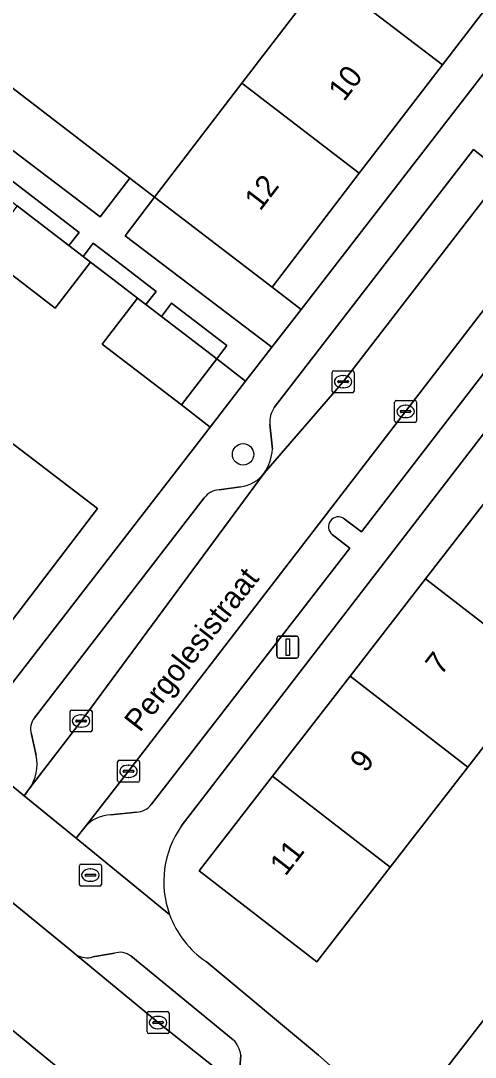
# Model space of a CAD drawing. Extents: x 159039 to 160102, y 381214 to 382524.
# Drawn here: x 159263.73 to 159284.46, y 381529.08 to 381576.34 of the extents above; entities that cross this region are included whole.
import ezdxf

# ---------------------------------------------------------------- set-up
doc = ezdxf.new("R2010")
doc.units = 0
for name, color, linetype in [('IMGEO_Boom', 7, 'Continuous'), ('IMGEO_Brandkraan', 7, 'Continuous'), ('IMGEO_Erf', 7, 'Continuous'), ('IMGEO_Groenvoorziening', 7, 'Continuous'), ('IMGEO_Kolk', 7, 'Continuous'), ('IMGEO_Lichtmast', 7, 'Continuous'), ('IMGEO_Openbare_ruimte_label', 7, 'Continuous'), ('IMGEO_Pand', 7, 'Continuous'), ('IMGEO_Pand_nummerreeks', 7, 'Continuous'), ('IMGEO_Parkeervlak_open', 7, 'Continuous'), ('IMGEO_Rijbaan_lokaal_open', 7, 'Continuous'), ('IMGEO_Voetpad_open', 7, 'Continuous')]:
    doc.layers.add(name, color=color, linetype=linetype)

msp = doc.modelspace()

# ---------------------------------------------------------------- linework, layer by layer
at = {"layer": 'IMGEO_Boom'}
msp.add_circle((159273.87, 381556.568), 0.489, dxfattribs=at)
at = {"layer": 'IMGEO_Brandkraan'}
for p, q in [((159266.408, 381536.956), (159266.408, 381537.808)), ((159266.483, 381537.882), (159267.335, 381537.882)), ((159266.896, 381537.662), (159266.921, 381537.662)), ((159267.409, 381537.808), (159267.409, 381536.956)), ((159266.667, 381537.376), (159266.667, 381537.388)), ((159267.105, 381537.339), (159266.707, 381537.339)), ((159266.71, 381537.425), (159267.108, 381537.425)), ((159266.919, 381537.102), (159266.894, 381537.102)), ((159267.151, 381537.388), (159267.151, 381537.376)), ((159267.335, 381536.882), (159266.483, 381536.882))]:
    msp.add_line(p, q, dxfattribs=at)
for points in [[(159266.408, 381536.956), (159266.408, 381537.808)], [(159266.483, 381537.882), (159267.335, 381537.882)], [(159267.409, 381537.808), (159267.409, 381536.956)], [(159267.335, 381536.882), (159266.483, 381536.882)]]:
    msp.add_lwpolyline(points, dxfattribs=at)
for centre, radius, start, end in [((159266.485, 381537.806), 0.0765, 91.552, 178.448), ((159266.485, 381537.806), 0.0765, 91.552, 178.448), ((159267.333, 381537.806), 0.0765, 1.552, 88.448), ((159267.333, 381537.806), 0.0765, 1.552, 88.448), ((159266.707, 381537.385), 0.0403, 85.8775, 175.7526), ((159266.704, 381537.375), 0.0366, 178.938, 274.7102), ((159267.108, 381537.382), 0.043, 264.8664, 352.4533), ((159267.112, 381537.387), 0.0386, 1.7309, 96.639), ((159266.485, 381536.958), 0.0765, 181.552, 268.448), ((159266.485, 381536.958), 0.0765, 181.552, 268.448), ((159267.333, 381536.958), 0.0765, 271.552, 358.448), ((159267.333, 381536.958), 0.0765, 271.552, 358.448)]:
    msp.add_arc(centre, radius, start, end, dxfattribs=at)
for centre, major_axis, ratio, start_param, end_param in [((159266.895, 381537.382), (-0.387, 0.002), 0.722429, 4.712389, 7.853982), ((159266.92, 381537.382), (-0.39, 0.002), 0.717154, 1.570796, 4.712389)]:
    msp.add_ellipse(centre, major_axis=major_axis, ratio=ratio, start_param=start_param, end_param=end_param, dxfattribs=at)
at = {"layer": 'IMGEO_Erf'}
for points in [[(159299.551, 381592.96), (159298.091, 381594.079), (159294.348, 381589.194), (159290.532, 381584.215), (159286.641, 381579.137), (159282.958, 381574.331), (159279.168, 381569.384), (159275.191, 381564.195), (159276.512, 381563.173)], [(159284.112, 381542.306), (159280.576, 381537.741), (159277.232, 381533.425), (159271.871, 381537.579), (159275.215, 381541.895), (159278.751, 381546.459), (159282.191, 381550.899), (159285.558, 381555.245), (159289.08, 381559.791), (159292.511, 381564.22), (159297.872, 381560.066), (159294.441, 381555.638), (159290.919, 381551.092), (159287.552, 381546.746)]]:
    msp.add_lwpolyline(points, close=True, dxfattribs=at)
for points in [[(159259.234, 381576.433), (159268.71, 381569.162), (159269.835, 381568.299), (159273.812, 381573.488), (159277.602, 381578.435)], [(159261.962, 381565.796), (159257.471, 381569.237), (159254.749, 381571.323), (159254.989, 381569.613), (159254.037, 381568.427), (159252.746, 381568.172), (159251.602, 381568.976), (159251.387, 381570.516), (159248.601, 381566.929), (159247.971, 381566.118), (159252.45, 381562.686), (159256.94, 381559.245), (159261.298, 381555.906), (159261.655, 381555.632), (159262.975, 381557.354), (159267.229, 381554.093), (159265.91, 381552.372), (159261.821, 381547.037), (159257.209, 381550.571), (159252.851, 381553.911), (159248.361, 381557.351), (159243.882, 381560.783), (159241.386, 381557.502), (159258.08, 381544.802)], [(159296.955, 381546.416), (159299.454, 381549.642), (159301.579, 381547.996), (159302.602, 381549.316), (159300.477, 381550.962), (159303.956, 381555.453), (159306.081, 381553.807), (159307.411, 381555.524), (159307.658, 381555.842), (159293.244, 381568.431), (159292.895, 381567.979), (159271.052, 381539.613)], [(159262.507, 381545.066), (159272.367, 381557.814), (159271.062, 381558.823), (159267.444, 381561.595), (159269.054, 381563.696), (159267.929, 381564.558), (159266.916, 381565.334), (159265.306, 381563.234), (159261.962, 381565.796)], [(159272.188, 381533.437), (159277.302, 381529.172), (159283.05, 381524.08), (159285.339, 381527.035), (159283.214, 381528.681), (159286.611, 381533.065), (159290.148, 381537.63), (159292.453, 381540.606), (159294.578, 381538.96), (159295.713, 381540.424), (159297.219, 381542.368), (159295.094, 381544.014), (159296.955, 381546.416)]]:
    msp.add_lwpolyline(points, dxfattribs=at)
for centre, radius, start, end in [((159274.663, 381537.084), 4.409, 144.9927, 199.8758), ((159274.669, 381537.091), 4.417, 199.9364, 235.8246)]:
    msp.add_arc(centre, radius, start, end, dxfattribs=at)
at = {"layer": 'IMGEO_Groenvoorziening'}
for points in [[(159259.234, 381576.433), (159257.173, 381578.013), (159256.868, 381577.615), (159255.768, 381576.179), (159267.355, 381567.397), (159268.71, 381569.162)], [(159261.697, 381570.29), (159261.236, 381569.688), (159263.573, 381567.897), (159265.93, 381566.09), (159266.392, 381566.692)], [(159269.835, 381568.299), (159268.496, 381566.532), (159275.188, 381561.461), (159276.512, 381563.173), (159275.191, 381564.195)], [(159268.31, 381565.221), (159267.034, 381566.199), (159266.573, 381565.597), (159266.916, 381565.334), (159267.929, 381564.558), (159269.054, 381563.696), (159269.443, 381563.398), (159269.904, 381564)], [(159270.611, 381563.458), (159270.15, 381562.856), (159272.672, 381560.924), (159273.133, 381561.526)], [(159273.986, 381559.907), (159272.672, 381560.924), (159271.062, 381558.823), (159272.367, 381557.814)]]:
    msp.add_lwpolyline(points, close=True, dxfattribs=at)
at = {"layer": 'IMGEO_Kolk'}
for p, q in [((159277.931, 381559.455), (159277.931, 381560.307)), ((159278.006, 381560.381), (159278.858, 381560.381)), ((159278.932, 381560.307), (159278.932, 381559.455)), ((159278.19, 381559.875), (159278.19, 381559.887)), ((159278.628, 381559.838), (159278.23, 381559.838)), ((159278.233, 381559.924), (159278.631, 381559.924)), ((159278.419, 381560.161), (159278.444, 381560.161)), ((159278.674, 381559.887), (159278.674, 381559.875)), ((159278.858, 381559.381), (159278.006, 381559.381)), ((159278.442, 381559.601), (159278.417, 381559.601)), ((159280.781, 381558.098), (159280.781, 381558.95)), ((159280.856, 381559.024), (159281.708, 381559.024)), ((159281.269, 381558.804), (159281.294, 381558.804)), ((159281.782, 381558.95), (159281.782, 381558.098)), ((159281.04, 381558.518), (159281.04, 381558.53)), ((159281.478, 381558.481), (159281.08, 381558.481)), ((159281.083, 381558.567), (159281.481, 381558.567)), ((159281.524, 381558.53), (159281.524, 381558.518)), ((159281.708, 381558.024), (159280.856, 381558.024)), ((159281.292, 381558.244), (159281.267, 381558.244)), ((159265.983, 381543.983), (159265.983, 381544.835)), ((159266.058, 381544.909), (159266.91, 381544.909)), ((159266.471, 381544.689), (159266.496, 381544.689)), ((159266.984, 381544.835), (159266.984, 381543.983)), ((159266.242, 381544.403), (159266.242, 381544.415)), ((159266.68, 381544.366), (159266.282, 381544.366)), ((159266.285, 381544.452), (159266.683, 381544.452)), ((159266.494, 381544.129), (159266.469, 381544.129)), ((159266.726, 381544.415), (159266.726, 381544.403)), ((159266.91, 381543.909), (159266.058, 381543.909)), ((159268.145, 381541.691), (159268.145, 381542.543)), ((159268.22, 381542.617), (159269.072, 381542.617)), ((159268.633, 381542.397), (159268.658, 381542.397)), ((159269.146, 381542.543), (159269.146, 381541.691)), ((159268.404, 381542.111), (159268.404, 381542.123)), ((159268.842, 381542.074), (159268.444, 381542.074)), ((159268.447, 381542.16), (159268.845, 381542.16)), ((159268.656, 381541.837), (159268.631, 381541.837)), ((159268.888, 381542.123), (159268.888, 381542.111)), ((159269.072, 381541.617), (159268.22, 381541.617)), ((159269.491, 381530.232), (159269.491, 381531.084)), ((159269.566, 381531.158), (159270.418, 381531.158)), ((159269.979, 381530.938), (159270.004, 381530.938)), ((159270.492, 381531.084), (159270.492, 381530.232)), ((159269.75, 381530.652), (159269.75, 381530.664)), ((159270.188, 381530.615), (159269.79, 381530.615)), ((159269.793, 381530.701), (159270.191, 381530.701)), ((159270.234, 381530.664), (159270.234, 381530.652)), ((159270.418, 381530.158), (159269.566, 381530.158)), ((159270.002, 381530.378), (159269.977, 381530.378))]:
    msp.add_line(p, q, dxfattribs=at)
for points in [[(159277.931, 381559.455), (159277.931, 381560.307)], [(159278.006, 381560.381), (159278.858, 381560.381)], [(159278.932, 381560.307), (159278.932, 381559.455)], [(159278.858, 381559.381), (159278.006, 381559.381)], [(159280.781, 381558.098), (159280.781, 381558.95)], [(159280.856, 381559.024), (159281.708, 381559.024)], [(159281.782, 381558.95), (159281.782, 381558.098)], [(159281.708, 381558.024), (159280.856, 381558.024)], [(159265.983, 381543.983), (159265.983, 381544.835)], [(159266.058, 381544.909), (159266.91, 381544.909)], [(159266.984, 381544.835), (159266.984, 381543.983)], [(159266.91, 381543.909), (159266.058, 381543.909)], [(159268.145, 381541.691), (159268.145, 381542.543)], [(159268.22, 381542.617), (159269.072, 381542.617)], [(159269.146, 381542.543), (159269.146, 381541.691)], [(159269.072, 381541.617), (159268.22, 381541.617)], [(159269.491, 381530.232), (159269.491, 381531.084)], [(159269.566, 381531.158), (159270.418, 381531.158)], [(159270.492, 381531.084), (159270.492, 381530.232)], [(159270.418, 381530.158), (159269.566, 381530.158)]]:
    msp.add_lwpolyline(points, dxfattribs=at)
for centre, radius, start, end in [((159278.008, 381560.305), 0.0765, 91.552, 178.448), ((159278.008, 381560.305), 0.0765, 91.552, 178.448), ((159278.856, 381560.305), 0.0765, 1.552, 88.448), ((159278.856, 381560.305), 0.0765, 1.552, 88.448), ((159278.23, 381559.884), 0.0403, 85.8775, 175.7526), ((159278.227, 381559.874), 0.0366, 178.938, 274.7102), ((159278.631, 381559.881), 0.043, 264.8664, 352.4533), ((159278.635, 381559.886), 0.0386, 1.7309, 96.639), ((159278.008, 381559.457), 0.0765, 181.552, 268.448), ((159278.008, 381559.457), 0.0765, 181.552, 268.448), ((159278.856, 381559.457), 0.0765, 271.552, 358.448), ((159278.856, 381559.457), 0.0765, 271.552, 358.448), ((159280.858, 381558.948), 0.0765, 91.552, 178.448), ((159280.858, 381558.948), 0.0765, 91.552, 178.448), ((159281.706, 381558.948), 0.0765, 1.552, 88.448), ((159281.706, 381558.948), 0.0765, 1.552, 88.448), ((159281.08, 381558.527), 0.0403, 85.8775, 175.7526), ((159281.077, 381558.517), 0.0366, 178.938, 274.7102), ((159281.481, 381558.524), 0.043, 264.8664, 352.4533), ((159281.485, 381558.529), 0.0386, 1.7309, 96.639), ((159280.858, 381558.1), 0.0765, 181.552, 268.448), ((159280.858, 381558.1), 0.0765, 181.552, 268.448), ((159281.706, 381558.1), 0.0765, 271.552, 358.448), ((159281.706, 381558.1), 0.0765, 271.552, 358.448), ((159266.06, 381544.833), 0.0765, 91.552, 178.448), ((159266.06, 381544.833), 0.0765, 91.552, 178.448), ((159266.908, 381544.833), 0.0765, 1.552, 88.448), ((159266.908, 381544.833), 0.0765, 1.552, 88.448), ((159266.282, 381544.412), 0.0403, 85.8775, 175.7526), ((159266.279, 381544.402), 0.0366, 178.938, 274.7102), ((159266.683, 381544.409), 0.043, 264.8664, 352.4533), ((159266.687, 381544.414), 0.0386, 1.7309, 96.639), ((159266.06, 381543.985), 0.0765, 181.552, 268.448), ((159266.06, 381543.985), 0.0765, 181.552, 268.448), ((159266.908, 381543.985), 0.0765, 271.552, 358.448), ((159266.908, 381543.985), 0.0765, 271.552, 358.448), ((159268.222, 381542.541), 0.0765, 91.552, 178.448), ((159268.222, 381542.541), 0.0765, 91.552, 178.448), ((159269.07, 381542.541), 0.0765, 1.552, 88.448), ((159269.07, 381542.541), 0.0765, 1.552, 88.448), ((159268.444, 381542.12), 0.0403, 85.8775, 175.7526), ((159268.441, 381542.11), 0.0366, 178.938, 274.7102), ((159268.845, 381542.117), 0.043, 264.8664, 352.4533), ((159268.849, 381542.122), 0.0386, 1.7309, 96.639), ((159268.222, 381541.693), 0.0765, 181.552, 268.448), ((159268.222, 381541.693), 0.0765, 181.552, 268.448), ((159269.07, 381541.693), 0.0765, 271.552, 358.448), ((159269.07, 381541.693), 0.0765, 271.552, 358.448), ((159269.568, 381531.082), 0.0765, 91.552, 178.448), ((159269.568, 381531.082), 0.0765, 91.552, 178.448), ((159270.416, 381531.082), 0.0765, 1.552, 88.448), ((159270.416, 381531.082), 0.0765, 1.552, 88.448), ((159269.79, 381530.661), 0.0403, 85.8775, 175.7526), ((159269.787, 381530.651), 0.0366, 178.938, 274.7102), ((159270.191, 381530.658), 0.043, 264.8664, 352.4533), ((159270.195, 381530.663), 0.0386, 1.7309, 96.639), ((159269.568, 381530.234), 0.0765, 181.552, 268.448), ((159269.568, 381530.234), 0.0765, 181.552, 268.448), ((159270.416, 381530.234), 0.0765, 271.552, 358.448), ((159270.416, 381530.234), 0.0765, 271.552, 358.448)]:
    msp.add_arc(centre, radius, start, end, dxfattribs=at)
for centre, major_axis, ratio, start_param, end_param in [((159278.418, 381559.881), (-0.387, 0.002), 0.722429, 4.712389, 7.853982), ((159278.443, 381559.881), (-0.39, 0.002), 0.717154, 1.570796, 4.712389), ((159281.268, 381558.524), (-0.387, 0.002), 0.722429, 4.712389, 7.853982), ((159281.293, 381558.524), (-0.39, 0.002), 0.717154, 1.570796, 4.712389), ((159266.47, 381544.409), (-0.387, 0.002), 0.722429, 4.712389, 7.853982), ((159266.495, 381544.409), (-0.39, 0.002), 0.717154, 1.570796, 4.712389), ((159268.632, 381542.117), (-0.387, 0.002), 0.722429, 4.712389, 7.853982), ((159268.657, 381542.117), (-0.39, 0.002), 0.717154, 1.570796, 4.712389), ((159269.978, 381530.658), (-0.387, 0.002), 0.722429, 4.712389, 7.853982), ((159270.003, 381530.658), (-0.39, 0.002), 0.717154, 1.570796, 4.712389)]:
    msp.add_ellipse(centre, major_axis=major_axis, ratio=ratio, start_param=start_param, end_param=end_param, dxfattribs=at)
at = {"layer": 'IMGEO_Lichtmast'}
for p, q in [((159275.413, 381547.378), (159275.413, 381548.178)), ((159275.413, 381548.178), (159275.413, 381547.378)), ((159275.513, 381548.278), (159276.303, 381548.278)), ((159276.303, 381548.278), (159275.513, 381548.278)), ((159276.403, 381548.178), (159276.403, 381547.378)), ((159276.403, 381547.378), (159276.403, 381548.178)), ((159276.303, 381547.278), (159275.513, 381547.278)), ((159275.513, 381547.278), (159276.303, 381547.278))]:
    msp.add_line(p, q, dxfattribs=at)
msp.add_lwpolyline([(159275.833, 381548.153), (159275.983, 381548.153), (159275.983, 381547.403), (159275.833, 381547.403), (159275.833, 381548.153)], dxfattribs=at)
for centre, start, end in [((159275.513, 381548.178), 90, 180), ((159275.513, 381548.178), 90, 180), ((159276.303, 381548.178), 0, 90), ((159276.303, 381548.178), 360, 90), ((159275.513, 381547.378), 180, 270), ((159275.513, 381547.378), 180, 270), ((159276.303, 381547.378), 270, 0), ((159276.303, 381547.378), 270, 0)]:
    msp.add_arc(centre, 0.1, start, end, dxfattribs=at)
at = {"layer": 'IMGEO_Pand'}
for points in [[(159282.958, 381574.331), (159286.641, 381579.137), (159281.285, 381583.241), (159277.602, 381578.435)], [(159277.602, 381578.435), (159273.812, 381573.488), (159279.168, 381569.384), (159282.958, 381574.331)], [(159279.168, 381569.384), (159273.812, 381573.488), (159269.835, 381568.299), (159275.191, 381564.195)], [(159266.573, 381565.597), (159265.93, 381566.09), (159263.573, 381567.897), (159261.962, 381565.796), (159265.306, 381563.234), (159266.916, 381565.334)], [(159270.15, 381562.856), (159269.443, 381563.398), (159269.054, 381563.696), (159267.444, 381561.595), (159271.062, 381558.823), (159272.672, 381560.924)], [(159257.209, 381550.571), (159261.821, 381547.037), (159265.91, 381552.372), (159267.229, 381554.093), (159262.975, 381557.354), (159261.655, 381555.632), (159261.298, 381555.906)], [(159287.552, 381546.746), (159290.919, 381551.092), (159285.558, 381555.245), (159282.191, 381550.899)], [(159287.552, 381546.746), (159282.191, 381550.899), (159278.751, 381546.459), (159284.112, 381542.306)], [(159275.215, 381541.895), (159280.576, 381537.741), (159284.112, 381542.306), (159278.751, 381546.459)], [(159275.215, 381541.895), (159271.871, 381537.579), (159277.232, 381533.425), (159280.576, 381537.741)], [(159286.611, 381533.065), (159283.214, 381528.681), (159285.339, 381527.035), (159288.735, 381531.419)]]:
    msp.add_lwpolyline(points, close=True, dxfattribs=at)
at = {"layer": 'IMGEO_Parkeervlak_open'}
for points in [[(159274.834, 381555.715), (159278.433, 381559.88), (159292.006, 381577.483), (159301.01, 381589.13), (159302.361, 381590.883), (159302.639, 381591.221)], [(159290.512, 381570.535), (159281.281, 381558.525), (159268.645, 381542.119), (159266.664, 381539.584)], [(159285.168, 381569.844), (159284.372, 381570.466), (159275.287, 381558.699)], [(159278.481, 381553.634), (159279.273, 381553.028), (159290.269, 381567.313)], [(159275.087, 381557.935), (159275.206, 381556.803)], [(159264.122, 381541.313), (159266.486, 381544.408), (159274.834, 381555.715)], [(159273.759, 381555.08), (159272.776, 381554.957)], [(159272.1, 381554.593), (159264.355, 381544.556)], [(159269.694, 381540.61), (159278.734, 381552.297), (159277.932, 381552.912)], [(159264.219, 381543.805), (159264.432, 381542.831)], [(159267.846, 381540.135), (159269.016, 381540.247)], [(159266.264, 381533.753), (159269.992, 381530.657), (159273.92, 381527.538), (159273.694, 381528.174), (159273.765, 381529.174)], [(159268.004, 381533.816), (159267.026, 381533.659)], [(159273.421, 381529.877), (159268.747, 381533.696)]]:
    msp.add_lwpolyline(points, dxfattribs=at)
for centre, radius, start, end in [((159276.294, 381558.027), 1.21, 146.2908, 184.3698), ((159273.055, 381556.931), 2.155, 325.6502, 356.5975), ((159273.519, 381556.713), 1.65, 278.3444, 322.7961), ((159272.876, 381553.961), 1.001, 95.7508, 140.8507), ((159278.216, 381553.266), 0.454, 54.1906, 231.3116), ((159265.016, 381544.048), 0.834, 142.4891, 196.9817), ((159262.58, 381542.419), 1.898, 324.3636, 12.5523), ((159268.931, 381541.22), 0.976, 274.9718, 321.3572), ((159267.92, 381538.433), 1.704, 92.4875, 137.4985), ((159266.741, 381534.487), 0.875, 236.9513, 288.9838), ((159268.266, 381533.077), 0.784, 52.1298, 109.5212), ((159272.535, 381529.008), 1.242, 7.701, 44.4469)]:
    msp.add_arc(centre, radius, start, end, dxfattribs=at)
at = {"layer": 'IMGEO_Rijbaan_lokaal_open'}
msp.add_lwpolyline([(159290.512, 381570.535), (159292.832, 381573.573), (159293.439, 381574.373), (159294.54, 381575.75), (159303.363, 381587.253), (159304.34, 381588.487), (159304.721, 381588.989), (159305.117, 381589.477), (159303.958, 381590.421), (159302.774, 381591.386), (159302.639, 381591.221), (159302.361, 381590.883), (159301.01, 381589.13), (159292.006, 381577.483), (159278.433, 381559.88), (159274.834, 381555.715), (159266.486, 381544.408), (159264.122, 381541.313), (159263.89, 381541), (159266.26, 381539.068), (159266.664, 381539.584), (159268.645, 381542.119), (159281.281, 381558.525)], close=True, dxfattribs=at)
for points in [[(159230.284, 381555.722), (159238.362, 381549.804), (159239.339, 381549.072), (159242.969, 381546.354), (159248.2, 381542.427), (159256.706, 381535.766), (159269.617, 381525.152), (159272.501, 381522.717)], [(159274.407, 381527.151), (159273.92, 381527.538), (159269.992, 381530.657), (159266.264, 381533.753), (159266.069, 381533.916), (159259.958, 381538.894)]]:
    msp.add_lwpolyline(points, dxfattribs=at)
at = {"layer": 'IMGEO_Voetpad_open'}
for points in [[(159299.551, 381592.96), (159276.512, 381563.173), (159275.188, 381561.461), (159273.986, 381559.907), (159272.367, 381557.814), (159262.507, 381545.066)], [(159271.052, 381539.613), (159292.895, 381567.979), (159293.244, 381568.431), (159294.094, 381569.533), (159306.856, 381586.072)], [(159261.697, 381570.29), (159266.392, 381566.692), (159265.93, 381566.09), (159266.573, 381565.597), (159267.034, 381566.199), (159268.31, 381565.221), (159269.904, 381564), (159269.443, 381563.398), (159270.15, 381562.856), (159270.611, 381563.458), (159273.133, 381561.526), (159272.672, 381560.924), (159273.986, 381559.907), (159275.188, 381561.461), (159268.496, 381566.532), (159269.835, 381568.299), (159268.71, 381569.162), (159267.355, 381567.397), (159255.768, 381576.179)], [(159275.287, 381558.699), (159284.372, 381570.466)], [(159284.372, 381570.466), (159285.168, 381569.844)], [(159290.269, 381567.313), (159279.273, 381553.028), (159278.481, 381553.634)], [(159275.206, 381556.803), (159275.087, 381557.935)], [(159272.501, 381522.717), (159269.617, 381525.152), (159256.706, 381535.766), (159248.2, 381542.427), (159242.969, 381546.354), (159239.339, 381549.072), (159238.362, 381549.804), (159230.284, 381555.722)], [(159272.776, 381554.957), (159273.759, 381555.08)], [(159264.355, 381544.556), (159272.1, 381554.593)], [(159277.932, 381552.912), (159278.734, 381552.297), (159269.694, 381540.61)], [(159270.517, 381535.585), (159266.26, 381539.068), (159263.89, 381541), (159260.139, 381544.087)], [(159260.139, 381544.087), (159263.89, 381541), (159264.122, 381541.313)], [(159264.432, 381542.831), (159264.219, 381543.805)], [(159258.116, 381541.865), (159258.107, 381540.849), (159258.426, 381540.166), (159259.958, 381538.894), (159266.069, 381533.916), (159266.264, 381533.753)], [(159269.016, 381540.247), (159267.846, 381540.135)], [(159266.664, 381539.584), (159266.26, 381539.068), (159270.517, 381535.585)], [(159267.026, 381533.659), (159268.004, 381533.816)], [(159268.747, 381533.696), (159273.421, 381529.877)], [(159298.097, 381510.434), (159295.726, 381512.647), (159289.064, 381518.753), (159285.465, 381521.941), (159283.05, 381524.08), (159277.302, 381529.172), (159272.188, 381533.437)], [(159273.765, 381529.174), (159273.694, 381528.174), (159273.92, 381527.538), (159274.407, 381527.151)]]:
    msp.add_lwpolyline(points, dxfattribs=at)
for centre, radius, start, end in [((159276.294, 381558.027), 1.21, 146.2908, 184.3698), ((159273.055, 381556.931), 2.155, 325.6502, 356.5975), ((159273.519, 381556.713), 1.65, 278.3444, 322.7961), ((159272.876, 381553.961), 1.001, 95.7508, 140.8507), ((159278.216, 381553.266), 0.454, 54.1906, 231.3116), ((159265.016, 381544.048), 0.834, 142.4891, 196.9817), ((159262.58, 381542.419), 1.898, 324.3636, 12.5523), ((159268.931, 381541.22), 0.976, 274.9718, 321.3572), ((159267.92, 381538.433), 1.704, 92.4875, 137.4985), ((159274.663, 381537.084), 4.409, 144.9927, 199.8758), ((159274.669, 381537.091), 4.417, 199.9364, 235.8246), ((159266.741, 381534.487), 0.875, 236.9513, 288.9838), ((159268.266, 381533.077), 0.784, 52.1298, 109.5212), ((159272.535, 381529.008), 1.242, 7.701, 44.4469)]:
    msp.add_arc(centre, radius, start, end, dxfattribs=at)

# ---------------------------------------------------------------- texts
at = {"layer": 'IMGEO_Openbare_ruimte_label'}
msp.add_text('Pergolesistraat', height=1, rotation=52.1099, dxfattribs=at).set_placement((159269.166, 381543.855))
at = {"layer": 'IMGEO_Pand_nummerreeks'}
for s, rotation, p in [('10', 52.5372, (159278.471, 381572.617)), ('12', 52.5372, (159274.65, 381567.631)), ('7', 52.2334, (159282.894, 381546.452)), ('9', 52.2334, (159279.454, 381542.012)), ('11', 52.2334, (159275.803, 381537.3))]:
    msp.add_text(s, height=1, rotation=rotation, dxfattribs=at).set_placement(p)

doc.saveas('drawing.dxf')
